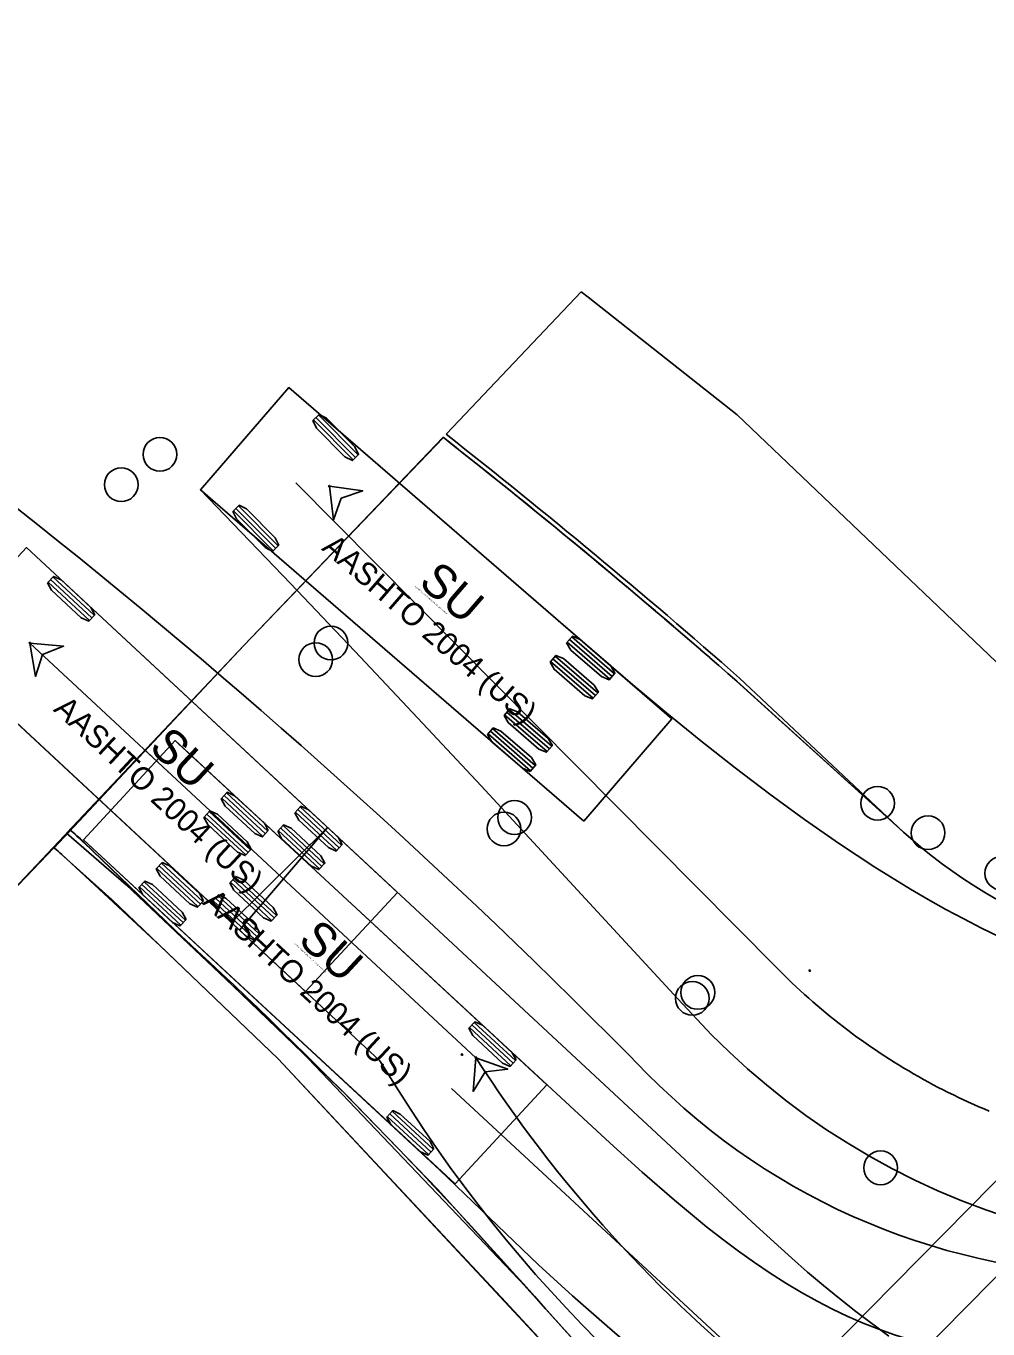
# Model space of a CAD drawing. Extents: x 2252379 to 2256472, y 13788212 to 13792539.
# Drawn here: x 2255390.1 to 2255447.1, y 13791369.5 to 13791446.6 of the extents above; entities that cross this region are included whole.
import ezdxf

# ---------------------------------------------------------------- set-up
doc = ezdxf.new("R2010")
doc.units = 0
for name, color, linetype in [('Bridge_Abutment', 7, 'Continuous'), ('D_TCP_OVERALL_PATT', 7, 'Continuous'), ('D_TCP_PH_1_ATVEHICLE', 7, 'Continuous'), ('D_TCP_PH_1_BARREL', 7, 'Continuous'), ('D_TCP_PH_1_CONST', 7, 'Continuous'), ('D_TCP_PH_1_PATT', 7, 'Continuous'), ('D_TCP_PH_1_WZPM_RMV_4IN_Y_SLD', 7, 'Continuous'), ('D_TCP_PH_1A_ATVEHICLE', 7, 'Continuous'), ('D_TCP_PH_1A_BARREL', 7, 'Continuous'), ('D_TCP_PH_1A_PATT', 7, 'Continuous'), ('D_TCP_PH_1B_BARREL', 7, 'Continuous'), ('D_TCP_PH_1B_PATT', 7, 'Continuous')]:
    doc.layers.add(name, color=color, linetype=linetype)

msp = doc.modelspace()

# ---------------------------------------------------------------- linework, layer by layer
at = {"layer": 'Bridge_Abutment'}
for p, q in [((2255388.77, 13791318.7), (2255468, 13791398.96)), ((2255391.617, 13791315.89), (2255470.847, 13791396.15))]:
    msp.add_line(p, q, dxfattribs=at)
at = {"layer": 'D_TCP_OVERALL_PATT'}
for p, q in [((2255422.991, 13791430.892), (2255415.043, 13791422.501)), ((2255415.043, 13791422.501), (2255414.999, 13791422.456)), ((2255414.824, 13791422.275), (2255403.022, 13791409.939)), ((2255414.824, 13791422.275), (2255403.022, 13791409.939)), ((2255403.022, 13791409.939), (2255392.518, 13791398.832)), ((2255403.022, 13791409.939), (2255392.724, 13791399.051)), ((2255442.088, 13791398.904), (2255432.205, 13791407.843)), ((2255442.088, 13791398.904), (2255432.205, 13791407.843)), ((2255432.382, 13791408.024), (2255442.088, 13791398.904)), ((2255392.713, 13791399.038), (2255384.179, 13791390.074)), ((2255392.518, 13791398.832), (2255396.056, 13791395.776)), ((2255392.698, 13791399.05), (2255392.713, 13791399.038)), ((2255393.54, 13791398.276), (2255401.991, 13791390.161)), ((2255396.056, 13791395.776), (2255406.018, 13791386.351)), ((2255401.991, 13791390.161), (2255406.018, 13791386.351)), ((2255406.018, 13791386.351), (2255419.694, 13791372)), ((2255406.018, 13791386.351), (2255406.655, 13791385.683))]:
    msp.add_line(p, q, dxfattribs=at)
for points in [[(2255448.428, 13791408.173), (2255432.237, 13791423.614), (2255423.405, 13791430.567), (2255422.991, 13791430.892)], [(2255452.618, 13791328.895), (2255426.066, 13791358.248), (2255426.424, 13791358.618), (2255427.065, 13791359.61), (2255427.403, 13791360.652), (2255427.433, 13791362.118), (2255426.935, 13791363.994), (2255414.487, 13791377.756), (2255409.102, 13791383.333), (2255393.54, 13791398.307)], [(2255426.935, 13791363.994), (2255414.487, 13791377.756), (2255409.102, 13791383.333), (2255393.54, 13791398.276)], [(2255406.655, 13791385.683), (2255409.102, 13791383.333), (2255414.487, 13791377.756), (2255419.694, 13791372), (2255426.935, 13791363.994)]]:
    msp.add_lwpolyline(points, dxfattribs=at)
msp.add_circle((2255415.94, 13791385.732), 0.0417, dxfattribs=at)
for centre, radius, start, end in [((2255149.097, 13791084.5), 430.021, 48.79391, 51.80457), ((2255462.257, 13791421.113), 30, 227.75639, 315.70035), ((2255462.257, 13791421.113), 30, 227.75639, 315.70035), ((2255462.257, 13791421.113), 30, 227.75639, 315.70035), ((2255384.513, 13791388.937), 13.01, 46.06991, 51.01614), ((2255321.162, 13791322.898), 104.5, 46.16331, 46.78004)]:
    msp.add_arc(centre, radius, start, end, dxfattribs=at)
msp.add_ellipse((2255149.115, 13791084.52), major_axis=(-307.76, 300.298), ratio=0.999411, start_param=4.766334, end_param=4.81888, dxfattribs=at)
msp.add_ellipse((2255149.115, 13791084.52), major_axis=(-307.76, 300.298), ratio=0.999411, start_param=4.766334, end_param=4.81888, dxfattribs=at)
at = {"layer": 'D_TCP_PH_1_ATVEHICLE'}
for p, q in [((2255405.681, 13791425.217), (2255400.449, 13791419.165)), ((2255428.376, 13791405.598), (2255405.681, 13791425.217)), ((2255407.137, 13791423.302), (2255409.483, 13791420.934)), ((2255407.285, 13791423.448), (2255409.631, 13791421.08)), ((2255407.433, 13791423.595), (2255409.779, 13791421.227)), ((2255434.546, 13791390.903), (2255406.091, 13791419.576)), ((2255400.449, 13791419.165), (2255423.145, 13791399.546)), ((2255400.449, 13791419.165), (2255400.449, 13791419.165)), ((2255402.402, 13791417.921), (2255404.752, 13791415.557)), ((2255402.55, 13791418.068), (2255404.9, 13791415.704)), ((2255402.697, 13791418.215), (2255405.048, 13791415.851)), ((2255422.168, 13791410.139), (2255424.689, 13791407.959)), ((2255422.304, 13791410.297), (2255424.826, 13791408.117)), ((2255422.44, 13791410.454), (2255424.962, 13791408.274)), ((2255421.459, 13791409.319), (2255423.981, 13791407.139)), ((2255421.187, 13791409.004), (2255423.708, 13791406.824)), ((2255421.323, 13791409.162), (2255423.845, 13791406.982)), ((2255418.734, 13791406.167), (2255421.256, 13791403.987)), ((2255418.462, 13791405.852), (2255420.984, 13791403.672)), ((2255418.598, 13791406.01), (2255421.12, 13791403.83)), ((2255423.145, 13791399.546), (2255428.376, 13791405.598)), ((2255417.481, 13791404.717), (2255420.003, 13791402.537)), ((2255417.617, 13791404.875), (2255420.139, 13791402.695)), ((2255417.753, 13791405.033), (2255420.275, 13791402.853)), ((2255398.946, 13791404.316), (2255393.513, 13791398.444)), ((2255420.966, 13791383.941), (2255398.946, 13791404.316)), ((2255404.149, 13791398.65), (2255401.703, 13791400.914)), ((2255404.291, 13791398.803), (2255401.844, 13791401.067)), ((2255404.432, 13791398.956), (2255401.985, 13791401.22)), ((2255403.272, 13791397.702), (2255400.825, 13791399.966)), ((2255403.413, 13791397.855), (2255400.967, 13791400.119)), ((2255403.13, 13791397.549), (2255400.684, 13791399.813)), ((2255393.513, 13791398.444), (2255415.532, 13791378.069)), ((2255400.442, 13791394.644), (2255397.995, 13791396.908)), ((2255400.583, 13791394.797), (2255398.137, 13791397.06)), ((2255400.3, 13791394.491), (2255397.854, 13791396.755)), ((2255399.282, 13791393.39), (2255396.835, 13791395.654)), ((2255399.423, 13791393.543), (2255396.977, 13791395.807)), ((2255399.565, 13791393.696), (2255397.118, 13791395.96)), ((2255419.112, 13791385.372), (2255416.665, 13791387.636)), ((2255418.829, 13791385.067), (2255416.382, 13791387.33)), ((2255418.97, 13791385.22), (2255416.524, 13791387.483)), ((2255415.532, 13791378.069), (2255420.966, 13791383.941)), ((2255420.966, 13791383.941), (2255420.966, 13791383.941)), ((2255415.313, 13791383.721), (2255434.732, 13791365.753)), ((2255414.103, 13791379.959), (2255411.656, 13791382.223)), ((2255414.244, 13791380.112), (2255411.798, 13791382.376)), ((2255413.961, 13791379.806), (2255411.515, 13791382.07))]:
    msp.add_line(p, q, dxfattribs=at)
for points in [[(2255448.409, 13791376.049), (2255446.964, 13791376.54), (2255445.536, 13791377.081), (2255444.132, 13791377.67), (2255442.755, 13791378.305), (2255441.404, 13791378.986), (2255440.084, 13791379.71), (2255438.794, 13791380.477), (2255437.536, 13791381.284), (2255436.312, 13791382.131), (2255435.122, 13791383.016), (2255433.967, 13791383.937), (2255432.848, 13791384.893), (2255431.764, 13791385.885), (2255430.717, 13791386.909), (2255428.715, 13791389.03), (2255417.07, 13791401.637), (2255413.32, 13791405.654), (2255409.581, 13791409.621), (2255405.778, 13791413.619), (2255400.449, 13791419.165), (2255405.681, 13791425.217), (2255421.776, 13791411.304), (2255426.066, 13791407.615), (2255428.073, 13791405.941), (2255430.092, 13791404.302), (2255432.123, 13791402.703), (2255434.169, 13791401.149), (2255436.23, 13791399.646), (2255438.306, 13791398.203), (2255440.396, 13791396.828), (2255442.497, 13791395.531), (2255443.551, 13791394.916), (2255444.606, 13791394.324), (2255445.661, 13791393.759), (2255446.716, 13791393.22), (2255447.768, 13791392.71)], [(2255408.082, 13791419.379), (2255408.335, 13791417.395), (2255408.786, 13791418.669), (2255410.064, 13791419.111), (2255408.082, 13791419.379)], [(2255447.64, 13791353.244), (2255446.903, 13791353.426), (2255446.171, 13791353.631), (2255445.447, 13791353.856), (2255444.73, 13791354.102), (2255444.022, 13791354.367), (2255443.322, 13791354.652), (2255442.632, 13791354.956), (2255441.951, 13791355.279), (2255441.282, 13791355.619), (2255439.975, 13791356.351), (2255438.713, 13791357.145), (2255437.5, 13791357.997), (2255436.339, 13791358.9), (2255435.233, 13791359.845), (2255425.573, 13791368.772), (2255424.528, 13791369.645), (2255422.477, 13791371.442), (2255420.474, 13791373.285), (2255414.621, 13791378.886), (2255393.513, 13791398.444), (2255398.946, 13791404.316), (2255399.119, 13791404.156), (2255399.119, 13791404.156)], [(2255399.119, 13791404.156), (2255424.686, 13791380.505), (2255426.609, 13791378.768), (2255428.521, 13791377.104), (2255430.423, 13791375.539), (2255431.371, 13791374.8), (2255432.315, 13791374.093), (2255433.256, 13791373.421), (2255434.193, 13791372.787), (2255435.124, 13791372.191), (2255436.049, 13791371.637), (2255436.967, 13791371.123), (2255437.878, 13791370.653), (2255438.784, 13791370.223), (2255439.699, 13791369.829), (2255440.625, 13791369.467), (2255441.56, 13791369.14), (2255442.506, 13791368.845), (2255443.463, 13791368.583), (2255444.427, 13791368.355), (2255445.399, 13791368.161), (2255446.378, 13791368.001), (2255447.361, 13791367.876)], [(2255447.17, 13791382.385), (2255446.862, 13791382.513), (2255446.556, 13791382.645), (2255446.251, 13791382.779), (2255445.947, 13791382.915), (2255445.644, 13791383.054), (2255445.342, 13791383.196), (2255445.042, 13791383.341), (2255444.743, 13791383.488), (2255444.445, 13791383.638), (2255444.149, 13791383.791), (2255443.854, 13791383.946), (2255443.56, 13791384.103), (2255443.268, 13791384.263), (2255442.977, 13791384.426), (2255442.687, 13791384.592), (2255442.399, 13791384.759), (2255442.113, 13791384.93), (2255441.828, 13791385.103), (2255441.544, 13791385.278), (2255441.263, 13791385.456), (2255440.982, 13791385.636), (2255440.703, 13791385.819), (2255440.426, 13791386.004), (2255440.151, 13791386.192), (2255439.877, 13791386.382), (2255439.605, 13791386.574), (2255439.334, 13791386.769), (2255439.066, 13791386.967), (2255438.799, 13791387.166), (2255438.533, 13791387.368), (2255438.27, 13791387.572), (2255438.008, 13791387.779), (2255437.749, 13791387.988), (2255437.491, 13791388.199), (2255437.235, 13791388.412), (2255436.98, 13791388.628), (2255436.728, 13791388.846), (2255436.478, 13791389.066), (2255436.229, 13791389.288), (2255435.983, 13791389.512), (2255435.738, 13791389.739), (2255435.496, 13791389.967), (2255435.255, 13791390.198), (2255435.017, 13791390.431), (2255434.78, 13791390.666), (2255434.546, 13791390.903)]]:
    msp.add_lwpolyline(points, dxfattribs=at)
for points in [[(2255407.101, 13791423.265), (2255407.47, 13791423.631), (2255407.91, 13791423.41), (2255409.599, 13791421.705), (2255409.816, 13791421.263), (2255409.446, 13791420.897), (2255409.007, 13791421.119), (2255407.318, 13791422.824)], [(2255408.082, 13791419.379), (2255408.335, 13791417.395), (2255408.786, 13791418.669), (2255410.064, 13791419.111)], [(2255402.365, 13791417.885), (2255402.734, 13791418.251), (2255403.174, 13791418.031), (2255404.866, 13791416.329), (2255405.084, 13791415.888), (2255404.716, 13791415.521), (2255404.275, 13791415.741), (2255402.583, 13791417.443)], [(2255422.134, 13791410.1), (2255422.474, 13791410.493), (2255422.93, 13791410.307), (2255424.745, 13791408.737), (2255424.996, 13791408.313), (2255424.656, 13791407.92), (2255424.2, 13791408.107), (2255422.385, 13791409.676)], [(2255421.153, 13791408.965), (2255421.493, 13791409.359), (2255421.949, 13791409.172), (2255423.764, 13791407.602), (2255424.015, 13791407.179), (2255423.675, 13791406.785), (2255423.219, 13791406.972), (2255421.404, 13791408.541)], [(2255418.428, 13791405.813), (2255418.768, 13791406.206), (2255419.224, 13791406.02), (2255421.039, 13791404.45), (2255421.29, 13791404.026), (2255420.95, 13791403.633), (2255420.494, 13791403.82), (2255418.679, 13791405.389)], [(2255417.447, 13791404.678), (2255417.787, 13791405.072), (2255418.243, 13791404.885), (2255420.058, 13791403.315), (2255420.309, 13791402.892), (2255419.969, 13791402.498), (2255419.513, 13791402.685), (2255417.698, 13791404.255)], [(2255404.467, 13791398.994), (2255404.114, 13791398.612), (2255403.665, 13791398.814), (2255401.904, 13791400.444), (2255401.667, 13791400.876), (2255402.021, 13791401.258), (2255402.47, 13791401.056), (2255404.231, 13791399.426)], [(2255403.448, 13791397.893), (2255403.095, 13791397.511), (2255402.646, 13791397.713), (2255400.885, 13791399.343), (2255400.649, 13791399.775), (2255401.002, 13791400.157), (2255401.451, 13791399.955), (2255403.212, 13791398.325)], [(2255400.619, 13791394.835), (2255400.265, 13791394.453), (2255399.816, 13791394.655), (2255398.055, 13791396.285), (2255397.819, 13791396.717), (2255398.172, 13791397.098), (2255398.621, 13791396.896), (2255400.382, 13791395.266)], [(2255399.6, 13791393.734), (2255399.247, 13791393.352), (2255398.798, 13791393.554), (2255397.036, 13791395.184), (2255396.8, 13791395.616), (2255397.153, 13791395.997), (2255397.602, 13791395.795), (2255399.364, 13791394.165)], [(2255419.147, 13791385.41), (2255418.794, 13791385.029), (2255418.345, 13791385.231), (2255416.583, 13791386.861), (2255416.347, 13791387.293), (2255416.7, 13791387.674), (2255417.149, 13791387.472), (2255418.911, 13791385.842)], [(2255414.279, 13791380.15), (2255413.926, 13791379.768), (2255413.477, 13791379.97), (2255411.716, 13791381.6), (2255411.48, 13791382.032), (2255411.833, 13791382.414), (2255412.282, 13791382.212), (2255414.043, 13791380.582)]]:
    msp.add_lwpolyline(points, close=True, dxfattribs=at)
for centre in [(2255408.082, 13791419.379), (2255436.536, 13791390.707), (2255436.536, 13791390.707)]:
    msp.add_circle(centre, 0.0417, dxfattribs=at)
at = {"layer": 'D_TCP_PH_1_BARREL'}
for centre in [(2255440.554, 13791400.607), (2255443.543, 13791398.862), (2255447.915, 13791396.461)]:
    msp.add_circle(centre, 1, dxfattribs=at)
at = {"layer": 'D_TCP_PH_1_CONST'}
msp.add_arc((2255197.178, 13791173.583), 298.15, 41.38262, 47.44054, dxfattribs=at)
at = {"layer": 'D_TCP_PH_1_PATT'}
for p, q in [((2255391.781, 13791397.98), (2255384.179, 13791390.074)), ((2255391.806, 13791397.948), (2255391.781, 13791397.98))]:
    msp.add_line(p, q, dxfattribs=at)
msp.add_lwpolyline([(2255452.618, 13791328.895), (2255422.605, 13791362.073), (2255423.097, 13791362.61), (2255423.516, 13791363.445), (2255423.655, 13791364.232), (2255423.591, 13791364.985), (2255422.846, 13791366.409), (2255405.058, 13791385.482), (2255398.065, 13791392.168), (2255392.227, 13791397.577)], dxfattribs=at)
msp.add_arc((2255387.718, 13791392.896), 6.499, 46.06991, 51.01614, dxfattribs=at)
at = {"layer": 'D_TCP_PH_1_WZPM_RMV_4IN_Y_SLD'}
for centre, radius, start, end in [((2255141.73, 13791104.116), 400, 44.52752, 58.8993), ((2255455.412, 13791412.667), 40, 224.52752, 315.70035)]:
    msp.add_arc(centre, radius, start, end, dxfattribs=at)
at = {"layer": 'D_TCP_PH_1A_ATVEHICLE'}
for p, q in [((2255390.14, 13791415.745), (2255384.695, 13791409.884)), ((2255412.12, 13791395.327), (2255390.14, 13791415.745)), ((2255391.566, 13791413.852), (2255394.008, 13791411.583)), ((2255391.708, 13791414.004), (2255394.15, 13791411.735)), ((2255391.424, 13791413.699), (2255393.866, 13791411.43)), ((2255416.762, 13791385.546), (2255390.348, 13791410.092)), ((2255384.695, 13791409.884), (2255406.675, 13791389.466)), ((2255406.077, 13791400.087), (2255408.519, 13791397.818)), ((2255406.219, 13791400.24), (2255408.661, 13791397.971)), ((2255406.361, 13791400.392), (2255408.803, 13791398.123)), ((2255405.34, 13791399.293), (2255407.782, 13791397.024)), ((2255405.056, 13791398.988), (2255407.498, 13791396.719)), ((2255405.198, 13791399.141), (2255407.64, 13791396.872)), ((2255402.504, 13791396.24), (2255404.946, 13791393.972)), ((2255402.22, 13791395.935), (2255404.663, 13791393.667)), ((2255402.362, 13791396.088), (2255404.804, 13791393.819)), ((2255406.675, 13791389.466), (2255412.12, 13791395.327)), ((2255401.2, 13791394.836), (2255403.642, 13791392.568)), ((2255401.341, 13791394.989), (2255403.783, 13791392.72)), ((2255401.483, 13791395.141), (2255403.925, 13791392.873))]:
    msp.add_line(p, q, dxfattribs=at)
for points in [[(2255423.979, 13791368.782), (2255423.028, 13791369.752), (2255422.1, 13791370.73), (2255421.192, 13791371.716), (2255420.299, 13791372.717), (2255419.42, 13791373.734), (2255418.556, 13791374.766), (2255417.706, 13791375.814), (2255416.871, 13791376.878), (2255416.051, 13791377.957), (2255415.245, 13791379.053), (2255414.455, 13791380.165), (2255413.679, 13791381.292), (2255412.919, 13791382.437), (2255412.175, 13791383.598), (2255411.079, 13791385.362), (2255402.764, 13791393.091), (2255407.965, 13791399.179), (2255402.276, 13791393.545), (2255384.695, 13791409.884), (2255390.14, 13791415.745), (2255433.372, 13791375.596), (2255435.474, 13791373.671), (2255436.408, 13791372.856), (2255437.35, 13791372.061), (2255438.299, 13791371.286), (2255439.263, 13791370.525), (2255441.215, 13791369.061)], [(2255390.348, 13791410.092), (2255390.682, 13791408.12), (2255391.081, 13791409.411), (2255392.339, 13791409.904), (2255390.348, 13791410.092)], [(2255416.762, 13791385.546), (2255416.598, 13791383.553), (2255417.304, 13791384.705), (2255418.645, 13791384.871), (2255416.762, 13791385.546)]]:
    msp.add_lwpolyline(points, dxfattribs=at)
for points in [[(2255391.389, 13791413.661), (2255391.743, 13791414.042), (2255392.192, 13791413.839), (2255393.95, 13791412.206), (2255394.185, 13791411.773), (2255393.831, 13791411.392), (2255393.383, 13791411.595), (2255391.624, 13791413.229)], [(2255390.348, 13791410.092), (2255390.682, 13791408.12), (2255391.081, 13791409.411), (2255392.339, 13791409.904)], [(2255406.042, 13791400.049), (2255406.396, 13791400.43), (2255406.844, 13791400.227), (2255408.603, 13791398.594), (2255408.838, 13791398.161), (2255408.484, 13791397.78), (2255408.036, 13791397.983), (2255406.277, 13791399.617)], [(2255405.021, 13791398.95), (2255405.375, 13791399.331), (2255405.824, 13791399.128), (2255407.582, 13791397.495), (2255407.817, 13791397.062), (2255407.463, 13791396.681), (2255407.015, 13791396.884), (2255405.256, 13791398.518)], [(2255402.185, 13791395.897), (2255402.539, 13791396.278), (2255402.988, 13791396.075), (2255404.746, 13791394.442), (2255404.981, 13791394.01), (2255404.627, 13791393.629), (2255404.179, 13791393.831), (2255402.421, 13791395.465)], [(2255401.164, 13791394.798), (2255401.518, 13791395.179), (2255401.967, 13791394.977), (2255403.725, 13791393.343), (2255403.96, 13791392.911), (2255403.607, 13791392.53), (2255403.158, 13791392.733), (2255401.4, 13791394.366)], [(2255416.762, 13791385.546), (2255416.598, 13791383.553), (2255417.304, 13791384.705), (2255418.645, 13791384.871)]]:
    msp.add_lwpolyline(points, close=True, dxfattribs=at)
for centre in [(2255390.348, 13791410.092), (2255416.762, 13791385.546), (2255416.762, 13791385.546)]:
    msp.add_circle(centre, 0.0417, dxfattribs=at)
msp.add_arc((2255484.855, 13791429.38), 80.982, 212.77118, 231.55249, dxfattribs=at)
at = {"layer": 'D_TCP_PH_1A_BARREL'}
for centre in [(2255395.755, 13791419.468), (2255407.271, 13791409.115), (2255418.425, 13791399.086), (2255429.579, 13791389.057), (2255440.734, 13791379.028), (2255440.734, 13791379.028)]:
    msp.add_circle(centre, 1, dxfattribs=at)
at = {"layer": 'D_TCP_PH_1A_PATT'}
for p, q in [((2255422.991, 13791430.892), (2255415.043, 13791422.501)), ((2255415.043, 13791422.501), (2255414.999, 13791422.456)), ((2255432.382, 13791408.024), (2255442.088, 13791398.904))]:
    msp.add_line(p, q, dxfattribs=at)
msp.add_lwpolyline([(2255448.428, 13791408.173), (2255432.237, 13791423.614), (2255423.405, 13791430.567), (2255422.991, 13791430.892)], dxfattribs=at)
for centre, radius, start, end in [((2255149.097, 13791084.5), 430.021, 48.79391, 51.80457), ((2255462.257, 13791421.113), 30, 227.75639, 315.70035)]:
    msp.add_arc(centre, radius, start, end, dxfattribs=at)
at = {"layer": 'D_TCP_PH_1B_BARREL'}
for centre in [(2255398.046, 13791421.264), (2255408.174, 13791410.094), (2255419.052, 13791399.764), (2255429.905, 13791389.409), (2255440.734, 13791379.028)]:
    msp.add_circle(centre, 1, dxfattribs=at)
at = {"layer": 'D_TCP_PH_1B_PATT'}
for p, q in [((2255414.844, 13791422.257), (2255403.022, 13791409.939)), ((2255403.022, 13791409.939), (2255391.78, 13791397.978)), ((2255442.088, 13791398.904), (2255432.216, 13791407.834)), ((2255391.78, 13791397.978), (2255395.204, 13791394.904)), ((2255395.204, 13791394.904), (2255405.058, 13791385.482)), ((2255405.058, 13791385.482), (2255418.525, 13791371.079))]:
    msp.add_line(p, q, dxfattribs=at)
msp.add_lwpolyline([(2255418.525, 13791371.079), (2255422.873, 13791366.379), (2255423.591, 13791364.985), (2255423.655, 13791364.232), (2255423.516, 13791363.445), (2255423.097, 13791362.61), (2255422.605, 13791362.073)], dxfattribs=at)
for centre, radius, start, end in [((2255149.115, 13791084.52), 429.742, 48.79391, 51.80457), ((2255462.257, 13791421.113), 30, 227.75639, 315.70035)]:
    msp.add_arc(centre, radius, start, end, dxfattribs=at)

# ---------------------------------------------------------------- texts
at = {"layer": 'D_TCP_PH_1_ATVEHICLE'}
for s, height, rotation, p in [('AASHTO 2004 (US)', 1.33333, 319.15719, (2255407.571, 13791415.644)), ('SU', 2, 319.15719, (2255413.293, 13791413.562)), ('(c) 2020 Transoft Solutions, Inc. All rights reserved.', 0.08, 319.15719, (2255413.147, 13791413.423)), ('AASHTO 2004 (US)', 1.33333, 317.22121, (2255400.512, 13791394.684)), ('SU', 2, 317.22121, (2255406.16, 13791392.409)), ('(c) 2020 Transoft Solutions, Inc. All rights reserved.', 0.08, 317.22121, (2255406.01, 13791392.275))]:
    msp.add_text(s, height=height, rotation=rotation, dxfattribs=at).set_placement(p)
at = {"layer": 'D_TCP_PH_1A_ATVEHICLE'}
for s, height, p in [('AASHTO 2004 (US)', 1.33333, (2255391.686, 13791406.11)), ('SU', 2, (2255397.33, 13791403.824)), ('(c) 2020 Transoft Solutions, Inc. All rights reserved.', 0.08, (2255397.18, 13791403.691))]:
    msp.add_text(s, height=height, rotation=317.10889, dxfattribs=at).set_placement(p)

doc.saveas('drawing.dxf')
